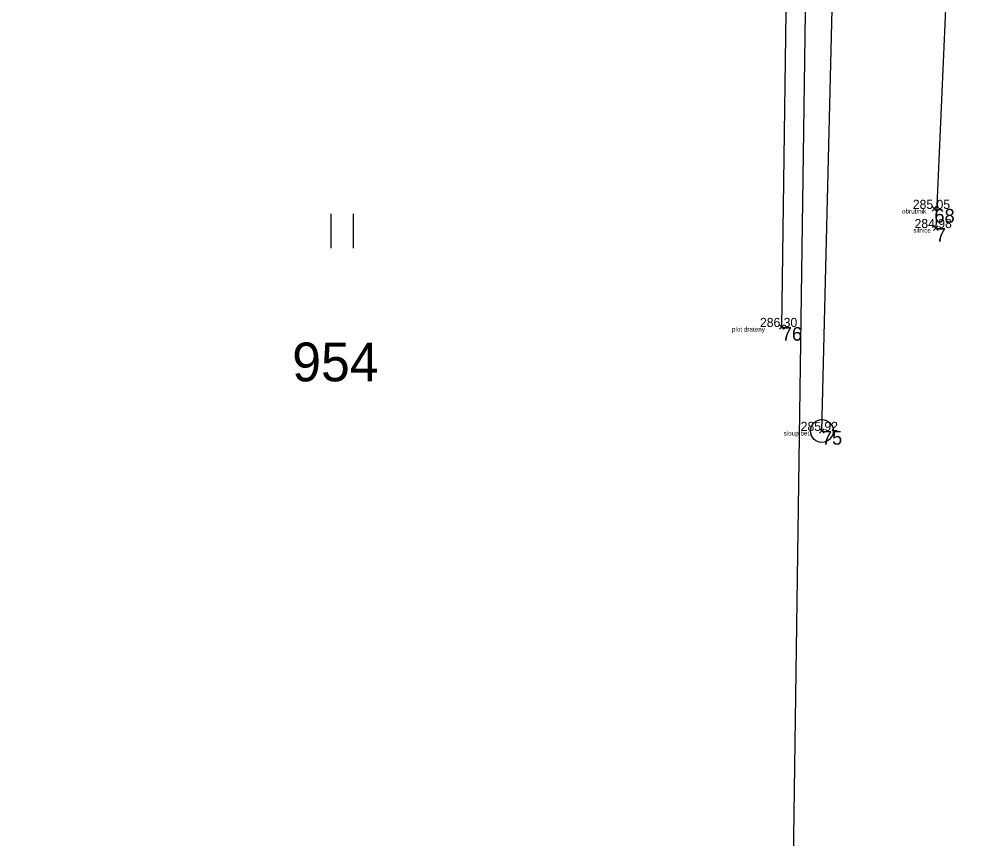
# Model space of a CAD drawing. Extents: x -456675 to -456278, y -1112395 to -1112217.
# Drawn here: x -456580.98 to -456559.85, y -1112328.73 to -1112310.75 of the extents above; entities that cross this region are included whole.
import ezdxf

# ---------------------------------------------------------------- set-up
doc = ezdxf.new("R2010")
doc.units = 0
for name, color, linetype in [('Cislo_bodu', 7, 'Continuous'), ('g_elektrina', 7, 'Continuous'), ('g_komunikace', 7, 'Continuous'), ('g_ploty', 7, 'Continuous'), ('Katastralni_mapa', 7, 'Continuous'), ('Kod_bodu', 7, 'Continuous'), ('Vyska_bodu', 7, 'Continuous'), ('Znacka_bodu', 7, 'Continuous')]:
    doc.layers.add(name, color=color, linetype=linetype)

msp = doc.modelspace()

# ---------------------------------------------------------------- linework, layer by layer
at = {"layer": 'g_elektrina'}
msp.add_lwpolyline([(-456563.36, -1112319.78), (-456562.97, -1112303.96), (-456562.3, -1112276.72)], dxfattribs=at)
msp.add_circle((-456563.36, -1112319.78), 0.25, dxfattribs=at)
at = {"layer": 'g_komunikace'}
msp.add_lwpolyline([(-456559.85, -1112290.05), (-456560.01, -1112295.66), (-456560.17, -1112301.1), (-456560.22, -1112302.34), (-456560.07, -1112302.34), (-456560.06, -1112302.68), (-456560.23, -1112302.68), (-456560.25, -1112303.02), (-456560.04, -1112303.02), (-456560.04, -1112303.31), (-456560.26, -1112303.32), (-456560.55, -1112308.36), (-456560.86, -1112315.33)], dxfattribs=at)
at = {"layer": 'g_ploty'}
msp.add_lwpolyline([(-456564.24, -1112317.5), (-456564.14, -1112310.05), (-456564.09, -1112304.42), (-456570.24, -1112304.71), (-456578.76, -1112305.1), (-456590.32, -1112305.79)], dxfattribs=at)
at = {"layer": 'Katastralni_mapa'}
for points in [[(-456563.64, -1112304.41), (-456564.02, -1112331.27)], [(-456574.14, -1112315.02), (-456574.14, -1112315.77)], [(-456573.64, -1112315.77), (-456573.64, -1112315.02)]]:
    msp.add_lwpolyline(points, dxfattribs=at)
at = {"layer": 'Znacka_bodu'}
for p, q in [((-456560.89, -1112314.91), (-456560.94, -1112314.86)), ((-456560.89, -1112314.91), (-456560.94, -1112314.96)), ((-456560.89, -1112314.91), (-456560.84, -1112314.86)), ((-456560.89, -1112314.91), (-456560.84, -1112314.96)), ((-456560.86, -1112315.33), (-456560.91, -1112315.28)), ((-456560.86, -1112315.33), (-456560.91, -1112315.38)), ((-456560.86, -1112315.33), (-456560.81, -1112315.28)), ((-456560.86, -1112315.33), (-456560.81, -1112315.38)), ((-456564.24, -1112317.5), (-456564.29, -1112317.45)), ((-456564.24, -1112317.5), (-456564.29, -1112317.55)), ((-456564.24, -1112317.5), (-456564.19, -1112317.45)), ((-456564.24, -1112317.5), (-456564.19, -1112317.55)), ((-456563.36, -1112319.78), (-456563.41, -1112319.73)), ((-456563.36, -1112319.78), (-456563.41, -1112319.83)), ((-456563.36, -1112319.78), (-456563.31, -1112319.73)), ((-456563.36, -1112319.78), (-456563.31, -1112319.83))]:
    msp.add_line(p, q, dxfattribs=at)

# ---------------------------------------------------------------- texts
at = {"layer": 'Cislo_bodu'}
for s, p in [('68', (-456560.89, -1112315.21)), ('7', (-456560.86, -1112315.63)), ('76', (-456564.24, -1112317.8)), ('75', (-456563.36, -1112320.08))]:
    msp.add_text(s, height=0.3, dxfattribs=at).set_placement(p)
at = {"layer": 'Katastralni_mapa'}
msp.add_text('954', height=0.85, dxfattribs=at).set_placement((-456574.988, -1112318.691))
at = {"layer": 'Kod_bodu'}
for s, p in [('obrubnik', (-456561.6, -1112315.01)), ('silnice', (-456561.351, -1112315.43)), ('plot drateny', (-456565.333, -1112317.6)), ('sloup bet.', (-456564.199, -1112319.88))]:
    msp.add_text(s, height=0.1, dxfattribs=at).set_placement(p)
at = {"layer": 'Vyska_bodu'}
for s, p in [('285.05', (-456561.363, -1112314.91)), ('284.98', (-456561.325, -1112315.33)), ('286.30', (-456564.719, -1112317.5)), ('285.92', (-456563.825, -1112319.78))]:
    msp.add_text(s, height=0.2, dxfattribs=at).set_placement(p)

doc.saveas('drawing.dxf')
